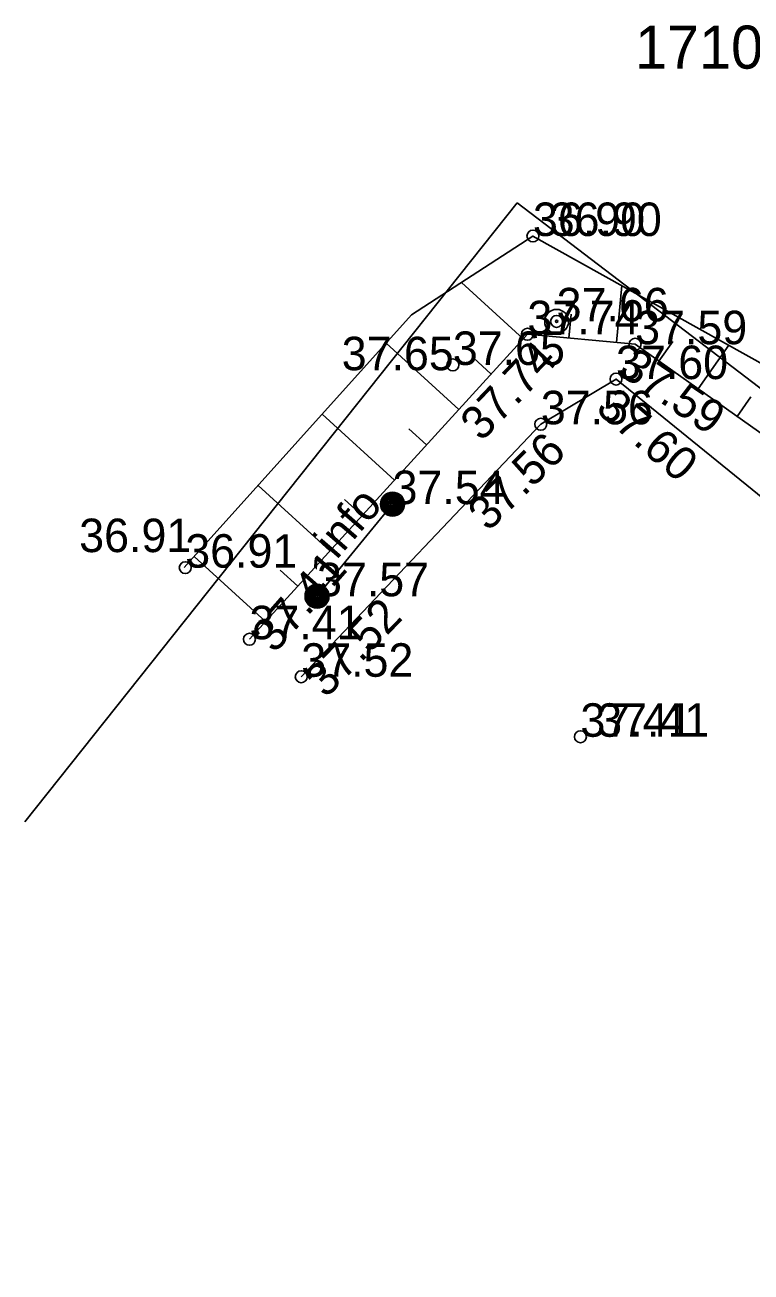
# Model space of a CAD drawing. Extents: x 627548 to 628052, y 6467984 to 6468802.
# Drawn here: x 627578.48 to 627593.66, y 6468733.86 to 6468759.94 of the extents above; entities that cross this region are included whole.
import ezdxf

# ---------------------------------------------------------------- set-up
doc = ezdxf.new("R2010")
doc.units = 0
for name, color, linetype in [('KORGUS-EH2000', 7, 'Continuous'), ('MOOTKORG-EH2000', 7, 'Continuous'), ('MOOTMPUNKT', 7, 'Continuous'), ('PIIR', 7, 'Continuous'), ('RAJATIS', 7, 'Continuous'), ('RELJEEF', 7, 'Continuous'), ('TEE', 7, 'Continuous')]:
    doc.layers.add(name, color=color, linetype=linetype)

msp = doc.modelspace()

# ---------------------------------------------------------------- linework, layer by layer
at = {"layer": 'MOOTMPUNKT'}
for centre in [(627589.097, 6468755.524), (627589.592, 6468753.739), (627588.98, 6468753.47), (627591.233, 6468753.261), (627587.423, 6468752.828), (627590.833, 6468752.532), (627589.261, 6468751.587), (627586.162, 6468749.918), (627581.829, 6468748.589), (627584.583, 6468747.991), (627583.171, 6468747.092), (627584.254, 6468746.308), (627590.09, 6468745.053)]:
    msp.add_circle(centre, 0.125, dxfattribs=at)
at = {"layer": 'PIIR'}
for p, q in [((627578.478, 6468743.276), (627588.77, 6468756.22)), ((627588.77, 6468756.22), (627618.05, 6468733.86))]:
    msp.add_line(p, q, dxfattribs=at)
at = {"layer": 'RAJATIS'}
msp.add_lwpolyline([(627586.162, 6468749.918), (627584.583, 6468747.991)], dxfattribs=at)
for centre, radius in [((627589.592, 6468753.739), 0.25), ((627589.592, 6468753.739), 0.0234), ((627586.162, 6468749.918), 0.25), ((627586.162, 6468749.918), 0.225), ((627586.162, 6468749.918), 0.2), ((627586.162, 6468749.918), 0.175), ((627586.162, 6468749.918), 0.15), ((627586.162, 6468749.918), 0.125), ((627586.162, 6468749.918), 0.1), ((627586.162, 6468749.918), 0.075), ((627586.162, 6468749.918), 0.05), ((627586.162, 6468749.918), 0.025), ((627584.583, 6468747.991), 0.25), ((627584.583, 6468747.991), 0.225), ((627584.583, 6468747.991), 0.2), ((627584.583, 6468747.991), 0.175), ((627584.583, 6468747.991), 0.15), ((627584.583, 6468747.991), 0.125), ((627584.583, 6468747.991), 0.1), ((627584.583, 6468747.991), 0.075), ((627584.583, 6468747.991), 0.05), ((627584.583, 6468747.991), 0.025)]:
    msp.add_circle(centre, radius, dxfattribs=at)
at = {"layer": 'RELJEEF'}
for p, q in [((627588.895, 6468753.376), (627587.601, 6468754.554)), ((627590.845, 6468753.297), (627590.956, 6468754.488)), ((627589.849, 6468753.389), (627589.896, 6468753.887)), ((627591.731, 6468752.908), (627592.02, 6468753.316)), ((627587.548, 6468751.898), (627586.025, 6468753.285)), ((627592.547, 6468752.33), (627593.192, 6468753.241)), ((627588.221, 6468752.637), (627587.852, 6468752.974)), ((627593.363, 6468751.753), (627593.652, 6468752.161)), ((627586.201, 6468750.419), (627584.688, 6468751.797)), ((627586.874, 6468751.158), (627586.505, 6468751.495)), ((627584.854, 6468748.94), (627583.351, 6468750.31)), ((627585.528, 6468749.68), (627585.158, 6468750.016)), ((627583.508, 6468747.462), (627582.014, 6468748.822)), ((627584.181, 6468748.201), (627583.811, 6468748.538))]:
    msp.add_line(p, q, dxfattribs=at)
for points in [[(627581.804, 6468748.589), (627586.557, 6468753.877), (627589.097, 6468755.524), (627601.41, 6468748.658), (627609.172, 6468741.833)], [(627583.171, 6468747.092), (627588.98, 6468753.47), (627591.233, 6468753.261), (627599.591, 6468747.343), (627608.852, 6468739.478)]]:
    msp.add_lwpolyline(points, dxfattribs=at)
at = {"layer": 'TEE'}
msp.add_lwpolyline([(627607.474, 6468738.895), (627598.002, 6468746.714), (627590.833, 6468752.532), (627589.261, 6468751.587), (627584.254, 6468746.308)], dxfattribs=at)

# ---------------------------------------------------------------- texts
at = {"layer": 'KORGUS-EH2000'}
for s, p in [('36.90', (627589.447, 6468755.524)), ('37.65', (627585.099, 6468752.717)), ('36.91', (627579.612, 6468748.914)), ('37.41', (627590.44, 6468745.053))]:
    msp.add_text(s, height=0.7, dxfattribs=at).set_placement(p)
for s, rotation, p in [('37.74', 46.3172, (627588.023, 6468751.207)), ('37.59', 325.8931, (627590.855, 6468752.652)), ('37.60', 319.1595, (627590.381, 6468751.877)), ('37.56', 44.9408, (627588.166, 6468749.327)), ('37.41', 48.6592, (627583.696, 6468746.778)), ('37.52', 46.0263, (627584.773, 6468745.842))]:
    msp.add_text(s, height=0.7, rotation=rotation, dxfattribs=at).set_placement(p)
at = {"layer": 'MOOTKORG-EH2000'}
for s, p in [('36.90', (627589.097, 6468755.524)), ('37.66', (627589.592, 6468753.739)), ('37.74', (627588.98, 6468753.47)), ('37.59', (627591.233, 6468753.261)), ('37.65', (627587.423, 6468752.828)), ('37.60', (627590.833, 6468752.532)), ('37.56', (627589.261, 6468751.587)), ('37.54', (627586.162, 6468749.918)), ('36.91', (627581.829, 6468748.589)), ('37.57', (627584.583, 6468747.991)), ('37.41', (627583.171, 6468747.092)), ('37.52', (627584.254, 6468746.308)), ('37.41', (627590.09, 6468745.053))]:
    msp.add_text(s, height=0.7, dxfattribs=at).set_placement(p)
at = {"layer": 'PIIR'}
msp.add_text('17101:001:0089', height=0.9, dxfattribs=at).set_placement((627591.23, 6468759.024))
at = {"layer": 'RAJATIS'}
msp.add_text('info', height=0.7, rotation=49.2215, dxfattribs=at).set_placement((627584.993, 6468748.741))

doc.saveas('drawing.dxf')
